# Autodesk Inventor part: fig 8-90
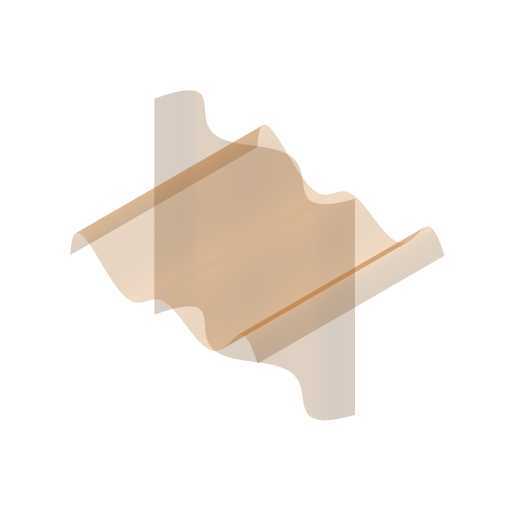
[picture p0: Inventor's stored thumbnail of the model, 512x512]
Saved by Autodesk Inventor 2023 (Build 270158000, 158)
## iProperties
Part Number: fig 8-90
Document SubType Name: Modeling
Created: 2003-08
Designer: Owner
Manufacturer: Standard
Standards Organization: Custom
Density: 1 g/cm^3
Material: Generic
Appearance: Default
Control State: 0
Master: False
Checked Out: False
Shininess: 64.0
Length Units: 11269
Angle Units: 11279
Time Units: 11290
Mass Units: 11283
Length Display Precision: 3
Angle Display Precision: 2
Compacted: True
Density: 0.0
Volumn: 0.0
Area: 0.0
PropertySet Name: Model Information
Author: Owner
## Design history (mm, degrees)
sketch "Sketch1"
  geometry: 7 further points
  constraints: 7 other
  dimensions: "d0" = 80 horizontal distance of point (40, 1.742) point (-40, -4.065); "d1" = 40 horizontal distance of point (0, 0) point (-40, -4.065)
extrude_surface "ExtrusionSrf1" sketch "Sketch1" dims "d2" = 80, "d3" = 0
sketch "Sketch2"
  geometry: L1 (40, 0)-(40, -40) reference; L2 (-40, 0)-(-40, -40) reference; 7 further points
  constraints: 2 point on line, 7 other
extrude_surface "ExtrusionSrf2" sketch "Sketch2" dims "d4" = 80, "d5" = 0
sketch "Sketch3"
  geometry: 2 further points
  constraints: 4 other
sketch "Sketch4"
  geometry: L1 (52.956, 12.425)-(-10.974, 12.425); A1 r 27.841 centre (-10.974, -15.416) between (-10.974, 12.425) and (-7.259, -43.008)
  constraints: 2 end point, 2 point on circle, 1 centre point, 1 horizontal, 1 tangent
body "Srf1"
body "Srf2"
